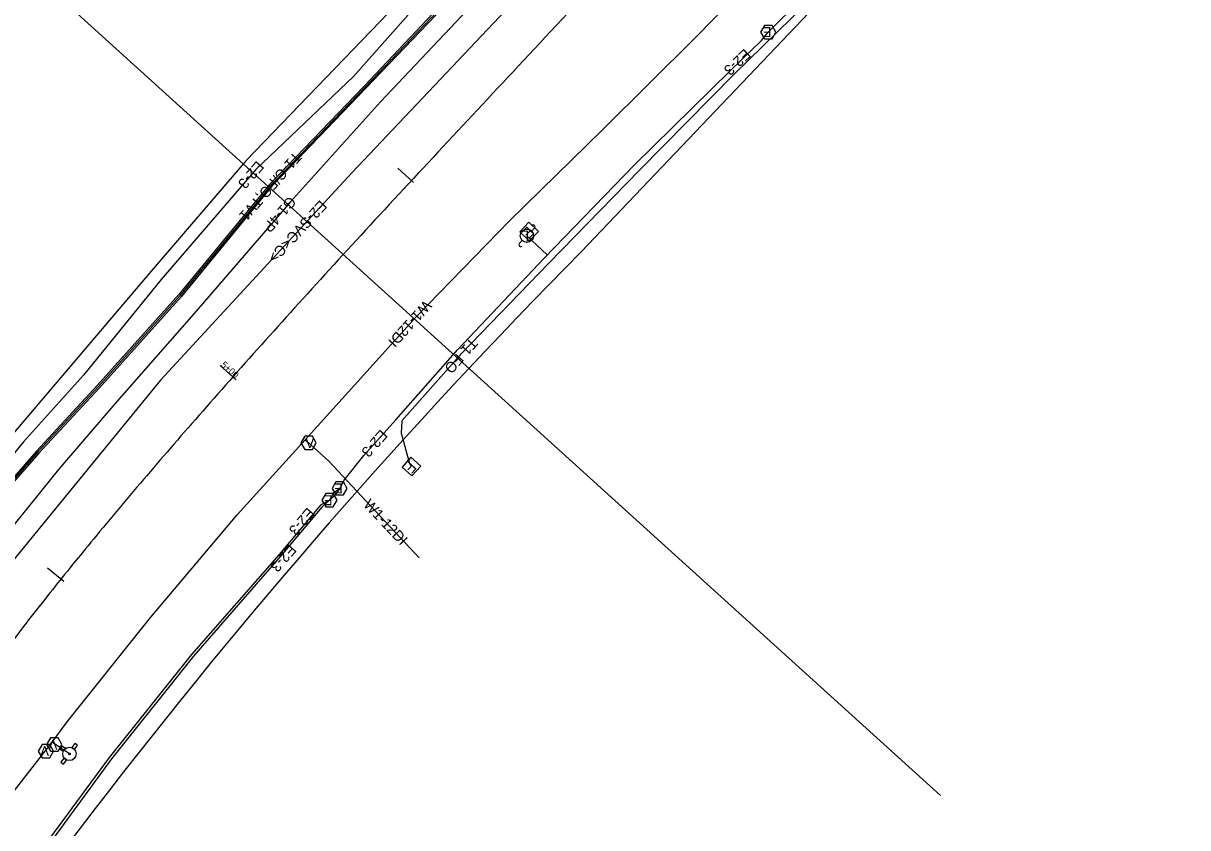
# Model space of a CAD drawing. Extents: x 1991878 to 2008544, y 770238 to 1141211.
# Drawn here: x 2008062.6 to 2008501.8, y 1139262.3 to 1139565.6 of the extents above; entities that cross this region are included whole.
import ezdxf

# ---------------------------------------------------------------- set-up
doc = ezdxf.new("R2010")
doc.units = 0
for name, color, linetype in [('RD_EX_SU_Elec', 7, 'Continuous'), ('RD_EX_SU_Gas', 7, 'Continuous'), ('RD_EX_SU_H2O', 7, 'Continuous'), ('RD_EX_SU_Pole', 7, 'Continuous'), ('RD_EX_SU_SwpLmt', 7, 'Continuous'), ('RD_EX_SU_Telecom', 7, 'Continuous'), ('RD_EX_SU_TX_Elec', 7, 'Continuous'), ('RD_EX_SU_TX_Gas', 7, 'Continuous'), ('RD_EX_SU_TX_H2O', 7, 'Continuous'), ('RD_EX_SU_TX_Telecom', 7, 'Continuous'), ('RD_HC_Cl', 7, 'Continuous')]:
    doc.layers.add(name, color=color, linetype=linetype)

msp = doc.modelspace()

# ---------------------------------------------------------------- linework, layer by layer
at = {"layer": 'RD_EX_SU_Elec'}
msp.add_line((2008252.58, 1139485.49), (2008260.25, 1139478.26), dxfattribs=at)
for points in [[(2008343.6, 1139562.26), (2008380.32, 1139598.68), (2008425.97, 1139646.35), (2008371.23, 1139696.87), (2008253.32, 1139579.8), (2008186.59, 1139509.23), (2008114.35, 1139431), (2008055.21, 1139358.58), (2007994.21, 1139276.04), (2007935.15, 1139188.81), (2007828.1, 1139009.37), (2007792.89, 1138934.82)], [(2008220.69, 1139583.46), (2008187.13, 1139545.5), (2008150.28, 1139510.47), (2008114.69, 1139468.97), (2008085.37, 1139432.97), (2008062.76, 1139407.73), (2008017.56, 1139352.95)], [(2008181.96, 1139390.23), (2008183.69, 1139393.32), (2008191.13, 1139402.67), (2008203.1, 1139416.11), (2008226.56, 1139442.54), (2008259.12, 1139477.06), (2008293.16, 1139512.17), (2008329.3, 1139547.82), (2008341.04, 1139559.14), (2008343.6, 1139562.26)], [(2008181.96, 1139390.23), (2008179.67, 1139388.39), (2008178.12, 1139385.75), (2008174.68, 1139383.87), (2008159.09, 1139365.26), (2008126.09, 1139327.58), (2008095.06, 1139288.8), (2008065.45, 1139248.63)], [(2008181.96, 1139390.23), (2008180.17, 1139387.66), (2008178.12, 1139385.75), (2008175.18, 1139383.15), (2008159.79, 1139364.83), (2008126.86, 1139327.01), (2008095.88, 1139288.25), (2008066.34, 1139247.91)]]:
    msp.add_lwpolyline(points, dxfattribs=at)
for points in [[(2008340.71, 1139562.26), (2008342.16, 1139559.76), (2008345.04, 1139559.76), (2008346.49, 1139562.26), (2008345.04, 1139564.76), (2008342.16, 1139564.76)], [(2008253.47, 1139483.53), (2008256.95, 1139487.12), (2008253.36, 1139490.6), (2008249.88, 1139487.01)], [(2008179.07, 1139390.23), (2008180.51, 1139387.73), (2008183.4, 1139387.73), (2008184.84, 1139390.23), (2008183.4, 1139392.72), (2008180.51, 1139392.72)], [(2008175.23, 1139385.75), (2008176.68, 1139383.25), (2008179.56, 1139383.25), (2008181.01, 1139385.75), (2008179.56, 1139388.25), (2008176.68, 1139388.25)]]:
    msp.add_lwpolyline(points, close=True, dxfattribs=at)
at = {"layer": 'RD_EX_SU_Gas'}
msp.add_lwpolyline([(2008404.55, 1139750.7), (2008403.44, 1139749.58), (2008398.9, 1139744.83), (2008391.94, 1139734.83), (2008385.92, 1139728.82), (2008369.04, 1139711.9), (2008334.96, 1139675.4), (2008301.61, 1139643.32), (2008270.11, 1139611.37), (2008232.47, 1139573.05), (2008197.32, 1139535.98), (2008163.44, 1139498.28), (2008127.84, 1139456.99), (2008097.18, 1139422.1), (2008075.86, 1139397.4), (2008030.23, 1139340.85), (2007999.81, 1139301.13), (2007969.65, 1139260.73)], dxfattribs=at)
at = {"layer": 'RD_EX_SU_H2O'}
for p, q in [((2008077.21, 1139293.07), (2008076.45, 1139292.06)), ((2008076.45, 1139292.06), (2008077.74, 1139291.1)), ((2008078.52, 1139292.09), (2008077.21, 1139293.07)), ((2008082.13, 1139294.08), (2008080.92, 1139292.46)), ((2008081.95, 1139291.74), (2008083.14, 1139293.33)), ((2008083.14, 1139293.33), (2008082.13, 1139294.08)), ((2008078.03, 1139288.59), (2008076.85, 1139287.02)), ((2008077.86, 1139286.26), (2008079.01, 1139287.8)), ((2008076.85, 1139287.02), (2008077.86, 1139286.26))]:
    msp.add_line(p, q, dxfattribs=at)
for points in [[(2008019.12, 1139221.08), (2008048.48, 1139262.65), (2008073.58, 1139294.58), (2008079.22, 1139302.23), (2008110.71, 1139341.71), (2008143.34, 1139380.24), (2008168.92, 1139408.5), (2008210.81, 1139454.91), (2008245.96, 1139491.17), (2008281.21, 1139525.55), (2008316.14, 1139560.25), (2008351.07, 1139595.92), (2008385.58, 1139632.4), (2008419.77, 1139669.26), (2008455.08, 1139706.22), (2008458.85, 1139710.23), (2008459.45, 1139710.87)], [(2008168.94, 1139408.52), (2008169.7, 1139407.84), (2008177.93, 1139400.51), (2008195.43, 1139381.63), (2008211.89, 1139363.99)], [(2008080.05, 1139290.09), (2008079.28, 1139290.66), (2008074.17, 1139294.05), (2008073.55, 1139294.54)]]:
    msp.add_lwpolyline(points, dxfattribs=at)
for points in [[(2008173.13, 1139407.35), (2008171.69, 1139409.85), (2008168.8, 1139409.85), (2008167.36, 1139407.35), (2008168.8, 1139404.85), (2008171.69, 1139404.85)], [(2008068.28, 1139291.15), (2008069.72, 1139288.65), (2008072.61, 1139288.65), (2008074.05, 1139291.15), (2008072.61, 1139293.65), (2008069.72, 1139293.65)], [(2008071.41, 1139293.6), (2008072.86, 1139291.1), (2008075.74, 1139291.1), (2008077.19, 1139293.6), (2008075.74, 1139296.1), (2008072.86, 1139296.1)]]:
    msp.add_lwpolyline(points, close=True, dxfattribs=at)
for radius in [2.52, 0.315]:
    msp.add_circle((2008080.05, 1139290.09), radius, dxfattribs=at)
for start, end in [(127.4627, 156.43), (40.9022, 69.8785), (216.5559, 245.5322)]:
    msp.add_arc((2008080.05, 1139290.09), 2.52, start, end, dxfattribs=at)
at = {"layer": 'RD_EX_SU_Pole'}
for p, q in [((2008255.41, 1139488.31), (2008254.35, 1139487.25)), ((2008250.82, 1139483.72), (2008249.76, 1139482.66))]:
    msp.add_line(p, q, dxfattribs=at)
msp.add_circle((2008252.58, 1139485.49), 2.5, dxfattribs=at)
for centre, start, end in [((2008254.88, 1139488.84), 315, 135), ((2008250.29, 1139482.13), 135, 315)]:
    msp.add_arc(centre, 0.75, start, end, dxfattribs=at)
at = {"layer": 'RD_EX_SU_SwpLmt'}
for points in [[(2008308.62, 1139692.22), (2008303.98, 1139673.05), (2008302.61, 1139671.39), (2008217.14, 1139586.99), (2008146.65, 1139513.91), (2008110.85, 1139472.17), (2008058.97, 1139410.99), (2008013.6, 1139356.01), (2007982.19, 1139312.98), (2007954.73, 1139272.11), (2007894.74, 1139182.48), (2007866.63, 1139138.23), (2007843.93, 1139094.78), (2007785.35, 1138986.79)], [(2008501.79, 1139678.03), (2008454.81, 1139670.38), (2008273.17, 1139479.53)]]:
    msp.add_lwpolyline(points, dxfattribs=at)
msp.add_arc((2009858.48, 1137910.13), 2230.75, 135.28907, 163.89519, dxfattribs=at)
at = {"layer": 'RD_EX_SU_Telecom'}
for points in [[(2008305.4, 1139658.27), (2008303.69, 1139657.15), (2008296.15, 1139648.2), (2008264.57, 1139616.22), (2008225.94, 1139578.68), (2008191.19, 1139541.83), (2008155.65, 1139504.96), (2008121.25, 1139463.29), (2008090.5, 1139429.06), (2008067.62, 1139404.3), (2008020.3, 1139350.24), (2008000.26, 1139321.01), (2007991.22, 1139306.98), (2007963.62, 1139266.78), (2007931.75, 1139219.86)], [(2008305.4, 1139658.27), (2008304.18, 1139656.84), (2008296.58, 1139647.74), (2008264.95, 1139615.87), (2008226.45, 1139578.22), (2008191.55, 1139541.46), (2008156.07, 1139504.61), (2008121.74, 1139462.81), (2008090.98, 1139428.65), (2008068.11, 1139403.96), (2008020.75, 1139349.83), (2008000.71, 1139320.77), (2007991.64, 1139306.71), (2007964.15, 1139266.38), (2007932.21, 1139219.57)], [(2008305.4, 1139658.27), (2008304.81, 1139656.42), (2008297.07, 1139647.18), (2008265.35, 1139615.32), (2008226.85, 1139577.83), (2008191.88, 1139541.09), (2008156.34, 1139504.22), (2008122.19, 1139462.43), (2008091.39, 1139428.14), (2008068.51, 1139403.49), (2008021.17, 1139349.41), (2008001.14, 1139320.51), (2007992.13, 1139306.45), (2007964.8, 1139266.15), (2007932.81, 1139219.12)], [(2008305.4, 1139658.27), (2008306.31, 1139656.83), (2008317.12, 1139644.5), (2008326.86, 1139634.24), (2008351.55, 1139610.4), (2008363.7, 1139600.31), (2008371.53, 1139592.02), (2008371.51, 1139588.49), (2008368.63, 1139583.51), (2008330.84, 1139546.49), (2008295.07, 1139510.2), (2008260.86, 1139475.1), (2008227.88, 1139441.1), (2008205.45, 1139415.71), (2008205.11, 1139411.02), (2008208.34, 1139399.62), (2008209.03, 1139398.46)]]:
    msp.add_lwpolyline(points, dxfattribs=at)
msp.add_lwpolyline([(2008209.21, 1139394.93), (2008212.56, 1139398.64), (2008208.85, 1139401.99), (2008205.5, 1139398.28)], close=True, dxfattribs=at)
at = {"layer": 'RD_HC_Cl'}
for p, q in [((2007960.14, 1139680.51), (2008408.6, 1139274.45)), ((2008203.94, 1139510.91), (2008209.85, 1139505.52)), ((2008136.93, 1139436.51), (2008142.93, 1139431.21)), ((2008071.74, 1139360.29), (2008077.93, 1139355.22))]:
    msp.add_line(p, q, dxfattribs=at)
msp.add_open_spline([(2008468.44, 1139784.65), (2008330.54, 1139636.27), (2008112.04, 1139402.61), (2008010.65, 1139269.99), (2007954.96, 1139181.47), (2007845.36, 1139006.33), (2007807.05, 1138915.36), (2007714.1, 1138721), (2007657.93, 1138535.69), (2007584.82, 1138278.81), (2007557.24, 1138105.93), (2007524.47, 1137887.62), (2007511.86, 1137606.6), (2007518.19, 1137380.97), (2007535.52, 1137158.14), (2007573, 1136960.76), (2007648.83, 1136694.4), (2007817.41, 1136298.79), (2008044.24, 1135795.68), (2008373.08, 1135014.28)], degree=2, dxfattribs=at)

# ---------------------------------------------------------------- texts
at = {"layer": 'RD_EX_SU_Elec'}
for height, rotation, p in [(3.75, 180, (2008344.74, 1139564.14)), (4, 225.8916, (2008252.83, 1139489.33)), (3.75, 180, (2008183.09, 1139392.1)), (3.75, 180, (2008179.26, 1139387.62))]:
    msp.add_text('E', height=height, rotation=rotation, dxfattribs=at).set_placement(p)
at = {"layer": 'RD_EX_SU_H2O'}
msp.add_text('V', height=3.75, dxfattribs=at).set_placement((2008169.03, 1139405.47))
for p in [(2008072.37, 1139293.02), (2008075.51, 1139295.48)]:
    msp.add_text('V', height=3.75, rotation=180, dxfattribs=at).set_placement(p)
at = {"layer": 'RD_EX_SU_Pole'}
msp.add_text('L', height=4, rotation=180, dxfattribs=at).set_placement((2008253.4, 1139487.42))
at = {"layer": 'RD_EX_SU_Telecom'}
msp.add_text('F', height=4, rotation=227.9307, dxfattribs=at).set_placement((2008208.31, 1139400.64))
at = {"layer": 'RD_EX_SU_TX_Elec'}
for s, rotation, p in [('E2-3', 223.9452, (2008334.62, 1139556.28)), ('E2-3', 229.3829, (2008150.7, 1139513.99)), ('E2-SVC<C>', 227.2839, (2008174.59, 1139499.18)), ('E2-3', 228.3211, (2008197.4, 1139412.69)), ('E2-3', 230.0283, (2008169.79, 1139383.29)), ('E2-3', 228.9569, (2008162.97, 1139369.43))]:
    msp.add_text(s, height=4, rotation=rotation, dxfattribs=at).set_placement(p)
at = {"layer": 'RD_EX_SU_TX_Gas'}
msp.add_text('G1-4P', height=4, rotation=229.2231, dxfattribs=at).set_placement((2008162.87, 1139500.68))
at = {"layer": 'RD_EX_SU_TX_H2O'}
for rotation, p in [(227.9307, (2008214.02, 1139461.45)), (313.0182, (2008190.64, 1139383.83))]:
    msp.add_text('W1-12DI', height=4, rotation=rotation, dxfattribs=at).set_placement(p)
at = {"layer": 'RD_EX_SU_TX_Telecom'}
for s, rotation, p in [('T1-C/FO,TV1', 228.8624, (2008164.89, 1139517.47)), ('T1-FO', 228.5389, (2008231.39, 1139447.35))]:
    msp.add_text(s, height=4, rotation=rotation, dxfattribs=at).set_placement(p)
at = {"layer": 'RD_HC_Cl'}
msp.add_text('5+00', height=2.5, rotation=318.5304, dxfattribs=at).set_placement((2008136.93, 1139436.52))

doc.saveas('drawing.dxf')
